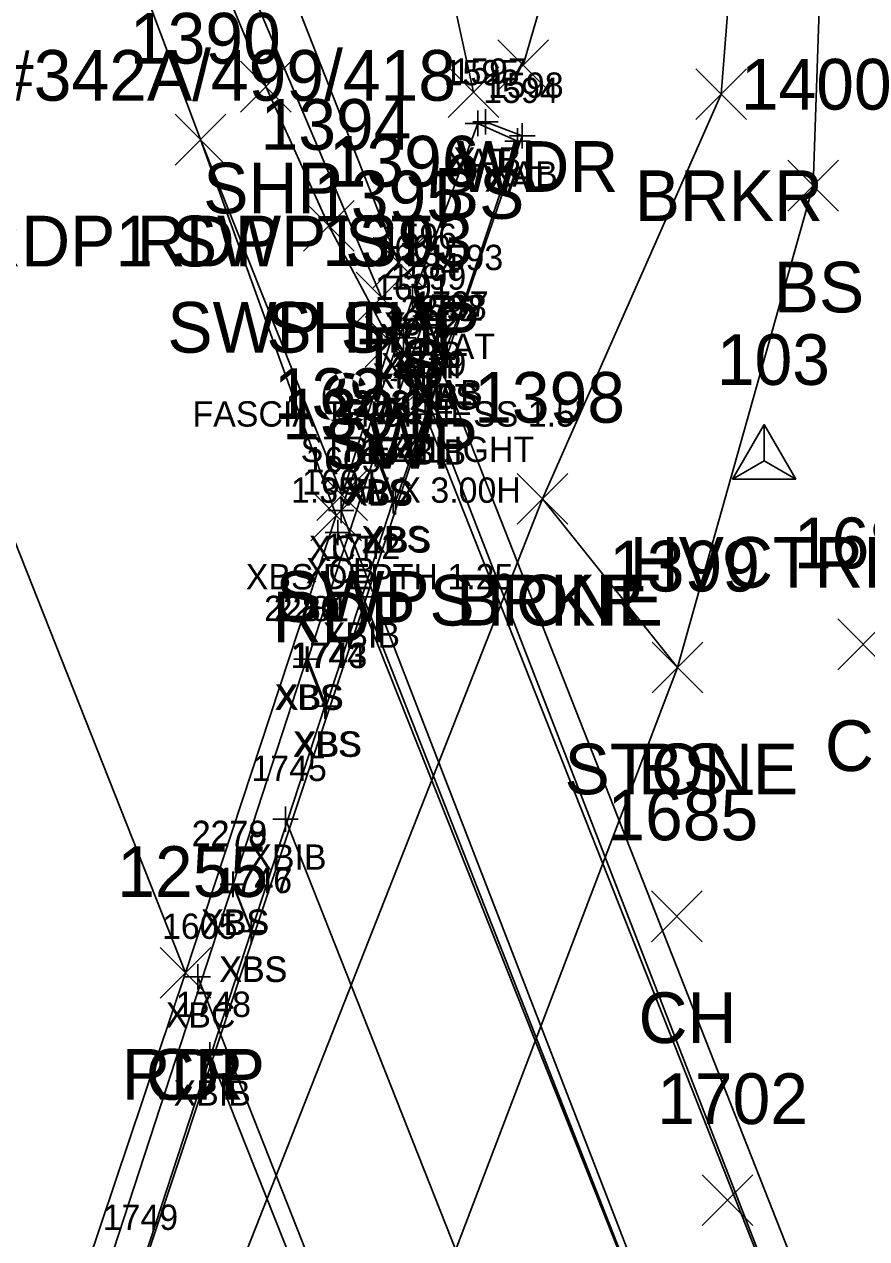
# Model space of a CAD drawing. Extents: x 1651305 to 1654558, y 539481 to 548441.
# Drawn here: x 1654313.41 to 1654346.64, y 544674.11 to 544722.01 of the extents above; entities that cross this region are included whole.
import ezdxf

# ---------------------------------------------------------------- set-up
doc = ezdxf.new("R2010")
doc.units = 0
for name, color, linetype in [('B_A', 7, 'Continuous'), ('B_C', 7, 'Continuous'), ('B_I', 7, 'Continuous'), ('B_TIC', 7, 'Continuous'), ('BB', 7, 'Continuous'), ('BDC', 7, 'Continuous'), ('BELB', 7, 'Continuous'), ('BF', 7, 'Continuous'), ('BR', 7, 'Continuous'), ('BSE', 7, 'Continuous'), ('BSUBM', 7, 'Continuous'), ('C_A', 7, 'Continuous'), ('C_I', 7, 'Continuous'), ('CPSM', 7, 'Continuous'), ('L_A', 7, 'Continuous'), ('L_I', 7, 'Continuous'), ('L_TIC', 7, 'Continuous'), ('LASF', 7, 'Continuous'), ('LAWA', 7, 'Continuous'), ('LAWE', 7, 'Continuous'), ('LELB', 7, 'Continuous'), ('P_A', 7, 'Continuous'), ('P_I', 7, 'Continuous'), ('P_TIC', 7, 'Continuous'), ('PET', 7, 'Continuous'), ('PRC', 7, 'Continuous'), ('PSP', 7, 'Continuous'), ('R_A', 7, 'Continuous'), ('R_I', 7, 'Continuous'), ('R_TIC', 7, 'Continuous'), ('RGR', 7, 'Continuous'), ('RSW', 7, 'Continuous'), ('U_C', 7, 'Continuous')]:
    doc.layers.add(name, color=color, linetype=linetype)

msp = doc.modelspace()

# ---------------------------------------------------------------- linework, layer by layer
at = {"layer": 'B_TIC'}
for p, q in [((1654331.298, 544718.108), (1654331.374, 544718.108)), ((1654331.607, 544718.167), (1654331.683, 544718.167)), ((1654332.861, 544717.411), (1654332.937, 544717.411)), ((1654333.056, 544717.613), (1654333.132, 544717.613)), ((1654328.88, 544711.655), (1654328.955, 544711.655)), ((1654328.88, 544711.655), (1654328.955, 544711.655)), ((1654328.721, 544711.198), (1654328.796, 544711.198)), ((1654330.672, 544710.818), (1654330.748, 544710.818)), ((1654329.233, 544710.496), (1654329.309, 544710.496)), ((1654329.218, 544710.048), (1654329.294, 544710.048)), ((1654329.218, 544710.048), (1654329.294, 544710.048)), ((1654329.218, 544710.048), (1654329.294, 544710.048)), ((1654328.368, 544709.646), (1654328.444, 544709.646)), ((1654329.887, 544708.806), (1654329.963, 544708.806)), ((1654329.894, 544708.829), (1654329.97, 544708.829)), ((1654329.894, 544708.829), (1654329.97, 544708.829)), ((1654330.023, 544708.857), (1654330.099, 544708.857)), ((1654330.098, 544708.982), (1654330.173, 544708.982)), ((1654328.993, 544708.249), (1654329.069, 544708.249)), ((1654329.22, 544706.64), (1654329.296, 544706.64)), ((1654327.25, 544705.075), (1654327.325, 544705.075)), ((1654327.332, 544705.024), (1654327.408, 544705.024)), ((1654327.966, 544703.224), (1654328.042, 544703.224)), ((1654328.048, 544703.173), (1654328.124, 544703.173)), ((1654325.907, 544702.843), (1654325.983, 544702.843)), ((1654325.779, 544701.967), (1654325.854, 544701.967)), ((1654326.614, 544699.426), (1654326.689, 544699.426)), ((1654324.544, 544696.977), (1654324.62, 544696.977)), ((1654324.597, 544696.97), (1654324.672, 544696.97)), ((1654325.261, 544695.126), (1654325.336, 544695.126)), ((1654325.313, 544695.119), (1654325.388, 544695.119)), ((1654323.714, 544690.667), (1654323.789, 544690.667)), ((1654321.641, 544688.089), (1654321.716, 544688.089)), ((1654321.656, 544688.103), (1654321.731, 544688.103)), ((1654322.357, 544686.238), (1654322.433, 544686.238)), ((1654322.372, 544686.252), (1654322.448, 544686.252)), ((1654320.252, 544684.44), (1654320.327, 544684.44)), ((1654320.725, 544681.361), (1654320.801, 544681.361))]:
    msp.add_line(p, q, dxfattribs=at)
for points in [[(1654331.295, 544717.608), (1654331.295, 544718.608)], [(1654331.604, 544717.667), (1654331.604, 544718.667)], [(1654330.795, 544718.108), (1654331.795, 544718.108)], [(1654331.104, 544718.167), (1654332.104, 544718.167)], [(1654332.858, 544716.911), (1654332.858, 544717.911)], [(1654333.053, 544717.113), (1654333.053, 544718.113)], [(1654332.358, 544717.411), (1654333.358, 544717.411)], [(1654332.553, 544717.613), (1654333.553, 544717.613)], [(1654328.876, 544711.155), (1654328.876, 544712.155)], [(1654328.876, 544711.155), (1654328.876, 544712.155)], [(1654328.376, 544711.655), (1654329.376, 544711.655)], [(1654328.376, 544711.655), (1654329.376, 544711.655)], [(1654328.717, 544710.698), (1654328.717, 544711.698)], [(1654328.217, 544711.198), (1654329.217, 544711.198)], [(1654330.669, 544710.318), (1654330.669, 544711.318)], [(1654329.23, 544709.996), (1654329.23, 544710.996)], [(1654330.169, 544710.818), (1654331.169, 544710.818)], [(1654328.73, 544710.496), (1654329.73, 544710.496)], [(1654329.215, 544709.548), (1654329.215, 544710.548)], [(1654329.215, 544709.548), (1654329.215, 544710.548)], [(1654329.215, 544709.548), (1654329.215, 544710.548)], [(1654328.365, 544709.146), (1654328.365, 544710.146)], [(1654328.715, 544710.048), (1654329.715, 544710.048)], [(1654328.715, 544710.048), (1654329.715, 544710.048)], [(1654328.715, 544710.048), (1654329.715, 544710.048)], [(1654327.865, 544709.646), (1654328.865, 544709.646)], [(1654329.884, 544708.306), (1654329.884, 544709.306)], [(1654329.891, 544708.329), (1654329.891, 544709.329)], [(1654329.891, 544708.329), (1654329.891, 544709.329)], [(1654330.02, 544708.357), (1654330.02, 544709.357)], [(1654330.094, 544708.482), (1654330.094, 544709.482)], [(1654328.99, 544707.749), (1654328.99, 544708.749)], [(1654329.384, 544708.806), (1654330.384, 544708.806)], [(1654329.391, 544708.829), (1654330.391, 544708.829)], [(1654329.391, 544708.829), (1654330.391, 544708.829)], [(1654329.52, 544708.857), (1654330.52, 544708.857)], [(1654329.594, 544708.982), (1654330.594, 544708.982)], [(1654328.49, 544708.249), (1654329.49, 544708.249)], [(1654329.217, 544706.14), (1654329.217, 544707.14)], [(1654328.717, 544706.64), (1654329.717, 544706.64)], [(1654327.246, 544704.575), (1654327.246, 544705.575)], [(1654327.329, 544704.524), (1654327.329, 544705.524)], [(1654326.746, 544705.075), (1654327.746, 544705.075)], [(1654326.829, 544705.024), (1654327.829, 544705.024)], [(1654327.963, 544702.724), (1654327.963, 544703.724)], [(1654328.045, 544702.673), (1654328.045, 544703.673)], [(1654325.904, 544702.343), (1654325.904, 544703.343)], [(1654327.463, 544703.224), (1654328.463, 544703.224)], [(1654327.545, 544703.173), (1654328.545, 544703.173)], [(1654325.404, 544702.843), (1654326.404, 544702.843)], [(1654325.775, 544701.467), (1654325.775, 544702.467)], [(1654325.275, 544701.967), (1654326.275, 544701.967)], [(1654326.61, 544698.926), (1654326.61, 544699.926)], [(1654326.11, 544699.426), (1654327.11, 544699.426)], [(1654324.541, 544696.477), (1654324.541, 544697.477)], [(1654324.593, 544696.47), (1654324.593, 544697.47)], [(1654324.041, 544696.977), (1654325.041, 544696.977)], [(1654324.093, 544696.97), (1654325.093, 544696.97)], [(1654325.257, 544694.626), (1654325.257, 544695.626)], [(1654325.309, 544694.619), (1654325.309, 544695.619)], [(1654324.757, 544695.126), (1654325.757, 544695.126)], [(1654324.809, 544695.119), (1654325.809, 544695.119)], [(1654323.71, 544690.167), (1654323.71, 544691.167)], [(1654323.21, 544690.667), (1654324.21, 544690.667)], [(1654321.637, 544687.589), (1654321.637, 544688.589)], [(1654321.652, 544687.603), (1654321.652, 544688.603)], [(1654321.137, 544688.089), (1654322.137, 544688.089)], [(1654321.152, 544688.103), (1654322.152, 544688.103)], [(1654322.354, 544685.738), (1654322.354, 544686.738)], [(1654322.369, 544685.752), (1654322.369, 544686.752)], [(1654321.854, 544686.238), (1654322.854, 544686.238)], [(1654321.869, 544686.252), (1654322.869, 544686.252)], [(1654320.248, 544683.94), (1654320.248, 544684.94)], [(1654319.748, 544684.44), (1654320.748, 544684.44)], [(1654320.722, 544680.861), (1654320.722, 544681.861)], [(1654320.222, 544681.361), (1654321.222, 544681.361)]]:
    msp.add_lwpolyline(points, dxfattribs=at)
at = {"layer": 'BB'}
for points in [[(1654329.217, 544706.64), (1654357.619, 544634.79)], [(1654326.61, 544699.426), (1654355.293, 544627.225)], [(1654323.71, 544690.667), (1654352.287, 544618.374)], [(1654320.722, 544681.361), (1654349.259, 544609.535)]]:
    msp.add_lwpolyline(points, dxfattribs=at)
at = {"layer": 'BDC'}
for points in [[(1654329.215, 544710.048), (1654328.717, 544711.198), (1654325.904, 544702.843), (1654343.99, 544656.168), (1654356.815, 544626.314), (1654359.561, 544633.364), (1654359.473, 544633.501)], [(1654325.775, 544701.967), (1654343.848, 544655.963), (1654356.322, 544625.929)]]:
    msp.add_lwpolyline(points, dxfattribs=at)
at = {"layer": 'BELB'}
msp.add_lwpolyline([(1654320.248, 544684.44), (1654335.991, 544644.535), (1654350.441, 544607.388)], dxfattribs=at)
at = {"layer": 'BF'}
msp.add_lwpolyline([(1654329.215, 544710.048), (1654348.537, 544660.985), (1654359.473, 544633.501)], dxfattribs=at)
at = {"layer": 'BR'}
msp.add_lwpolyline([(1654329.215, 544710.048), (1654328.365, 544709.646), (1654348.062, 544658.92), (1654358.364, 544633.155), (1654359.473, 544633.501)], dxfattribs=at)
at = {"layer": 'BSE'}
for points in [[(1654330.02, 544708.857), (1654328.045, 544703.173), (1654327.963, 544703.224), (1654325.309, 544695.119), (1654325.257, 544695.126), (1654322.369, 544686.252), (1654322.354, 544686.238), (1654314.152, 544661.138), (1654313.436, 544662.989), (1654321.637, 544688.089), (1654321.652, 544688.103), (1654324.541, 544696.977), (1654324.593, 544696.97), (1654327.246, 544705.075), (1654327.329, 544705.024), (1654329.23, 544710.496), (1654329.884, 544708.806)], [(1654329.884, 544708.806), (1654330.02, 544708.857)], [(1654327.246, 544705.075), (1654327.963, 544703.224)], [(1654327.329, 544705.024), (1654328.045, 544703.173)], [(1654324.541, 544696.977), (1654325.257, 544695.126)], [(1654324.593, 544696.97), (1654325.309, 544695.119)], [(1654321.637, 544688.089), (1654322.354, 544686.238)], [(1654321.652, 544688.103), (1654322.369, 544686.252)]]:
    msp.add_lwpolyline(points, dxfattribs=at)
at = {"layer": 'BSUBM'}
for points in [[(1654331.604, 544718.167), (1654333.053, 544717.613), (1654330.094, 544708.982), (1654313.851, 544660.207)], [(1654329.891, 544708.829), (1654330.669, 544710.818), (1654332.858, 544717.411), (1654331.295, 544718.108), (1654328.876, 544711.655)], [(1654329.891, 544708.829), (1654328.876, 544711.655)]]:
    msp.add_lwpolyline(points, dxfattribs=at)
at = {"layer": 'CPSM'}
for p, q in [((1654341.348, 544704.069), (1654342.598, 544706.234)), ((1654343.848, 544704.069), (1654342.598, 544706.234)), ((1654342.598, 544704.79), (1654342.598, 544706.234)), ((1654341.348, 544704.069), (1654342.598, 544704.79)), ((1654342.598, 544704.79), (1654342.598, 544704.79)), ((1654342.598, 544704.79), (1654343.848, 544704.069)), ((1654341.348, 544704.069), (1654343.848, 544704.069))]:
    msp.add_line(p, q, dxfattribs=at)
at = {"layer": 'L_TIC'}
for points in [[(1654332.089, 544719.406), (1654334.089, 544721.406)], [(1654334.089, 544719.406), (1654332.089, 544721.406)], [(1654330.123, 544718.343), (1654332.123, 544720.343)], [(1654332.123, 544718.343), (1654330.123, 544720.343)], [(1654339.893, 544718.253), (1654341.893, 544720.253)], [(1654341.893, 544718.253), (1654339.893, 544720.253)], [(1654343.529, 544714.65), (1654345.529, 544716.65)], [(1654345.529, 544714.65), (1654343.529, 544716.65)], [(1654327.163, 544711.614), (1654329.163, 544713.614)], [(1654329.163, 544711.614), (1654327.163, 544713.614)], [(1654332.845, 544702.3), (1654334.845, 544704.3)], [(1654334.845, 544702.3), (1654332.845, 544704.3)], [(1654332.845, 544702.3), (1654334.845, 544704.3)], [(1654334.845, 544702.3), (1654332.845, 544704.3)], [(1654345.503, 544696.559), (1654347.503, 544698.559)], [(1654347.503, 544696.559), (1654345.503, 544698.559)], [(1654338.174, 544695.643), (1654340.174, 544697.643)], [(1654340.174, 544695.643), (1654338.174, 544697.643)], [(1654338.174, 544695.643), (1654340.174, 544697.643)], [(1654340.174, 544695.643), (1654338.174, 544697.643)], [(1654338.147, 544685.83), (1654340.147, 544687.83)], [(1654340.147, 544685.83), (1654338.147, 544687.83)], [(1654340.142, 544674.636), (1654342.142, 544676.636)], [(1654342.142, 544674.636), (1654340.142, 544676.636)]]:
    msp.add_lwpolyline(points, dxfattribs=at)
at = {"layer": 'LASF'}
msp.add_lwpolyline([(1654333.845, 544703.3), (1654339.174, 544696.643)], dxfattribs=at)
at = {"layer": 'LAWA'}
msp.add_lwpolyline([(1654333.089, 544720.406), (1654339.568, 544742.787), (1654339.926, 544774.824), (1654333.777, 544809.516), (1654332.911, 544836.907), (1654333.19, 544866.217)], dxfattribs=at)
at = {"layer": 'LAWE'}
msp.add_lwpolyline([(1654242.515, 544465.967), (1654256.87, 544483.548), (1654283.123, 544539.875), (1654291.834, 544564.241), (1654301.763, 544593.784), (1654310.979, 544627.694), (1654314.699, 544654.654), (1654333.845, 544703.3), (1654340.893, 544719.253), (1654343.001, 544745.948), (1654343.543, 544777.003), (1654341.256, 544814.623), (1654342.705, 544842.641), (1654342.649, 544866.803)], dxfattribs=at)
at = {"layer": 'LELB'}
for points in [[(1654268.864, 544879.178), (1654276.493, 544842.278), (1654286.118, 544815.622), (1654299.147, 544783.593), (1654310.71, 544759.789), (1654316.885, 544741.298), (1654328.163, 544712.614)], [(1654321.982, 544868.568), (1654300.331, 544866.144), (1654280.17, 544869.383), (1654284.965, 544845.051), (1654295.376, 544825.082), (1654318.777, 544790.661), (1654321.652, 544762.863), (1654331.123, 544719.343)], [(1654243.655, 544463.614), (1654257.64, 544478.05), (1654284.349, 544538.419), (1654294.462, 544561.387), (1654312.806, 544626.029), (1654318.85, 544643.272), (1654339.174, 544696.643), (1654344.529, 544715.65), (1654345.587, 544746.872), (1654345.745, 544776.719), (1654344.633, 544815.202), (1654344.44, 544841.842), (1654343.526, 544866.969)]]:
    msp.add_lwpolyline(points, dxfattribs=at)
at = {"layer": 'P_TIC'}
for points in [[(1654321.93, 544718.555), (1654323.93, 544720.555)], [(1654323.93, 544718.555), (1654321.93, 544720.555)], [(1654319.353, 544716.464), (1654321.353, 544718.464)], [(1654321.353, 544716.464), (1654319.353, 544718.464)], [(1654324.421, 544713.063), (1654326.421, 544715.063)], [(1654326.421, 544713.063), (1654324.421, 544715.063)], [(1654324.712, 544701.64), (1654326.712, 544703.64)], [(1654326.712, 544701.64), (1654324.712, 544703.64)], [(1654324.712, 544701.64), (1654326.712, 544703.64)], [(1654326.712, 544701.64), (1654324.712, 544703.64)], [(1654318.767, 544683.597), (1654320.767, 544685.597)], [(1654320.767, 544683.597), (1654318.767, 544685.597)], [(1654318.767, 544683.597), (1654320.767, 544685.597)], [(1654320.767, 544683.597), (1654318.767, 544685.597)]]:
    msp.add_lwpolyline(points, dxfattribs=at)
at = {"layer": 'PET'}
for points in [[(1654139.13, 545176.501), (1654150.393, 545147.194), (1654157.161, 545131.709), (1654170.764, 545099.134), (1654178.155, 545080.649), (1654186.439, 545060.962), (1654201.827, 545022.365), (1654207.176, 545004.715), (1654219.138, 544973.235), (1654242.36, 544920.072), (1654247.532, 544907.575), (1654259.279, 544878.108), (1654268.455, 544853.759), (1654271.522, 544840.232), (1654282.762, 544813.426), (1654295.449, 544782.265), (1654306.751, 544753.721), (1654320.353, 544717.464), (1654325.712, 544702.64)], [(1654112.873, 545166.538), (1654122.035, 545140.208), (1654132.622, 545111.941), (1654135.362, 545108.194), (1654138.441, 545103.483), (1654151.391, 545069.682), (1654150.584, 545065.43), (1654160.56, 545041.116), (1654174.104, 545006.911), (1654181.292, 544989.927), (1654184.888, 544987.01), (1654195.032, 544961.541), (1654207.758, 544928.164), (1654222.993, 544890.413), (1654239.031, 544850.694), (1654252.069, 544818.679), (1654270.718, 544773.03), (1654287.358, 544732.427), (1654297.759, 544708.463), (1654313.88, 544667.099), (1654319.767, 544684.597), (1654325.712, 544702.64)]]:
    msp.add_lwpolyline(points, dxfattribs=at)
at = {"layer": 'PRC'}
msp.add_lwpolyline([(1654126.316, 545171.737), (1654141.33, 545133.412), (1654151.931, 545107.487), (1654165.206, 545072.693), (1654175.565, 545046.61), (1654188.965, 545011.94), (1654198.023, 544989.456), (1654207.449, 544965.611), (1654220.746, 544933.068), (1654235.659, 544895.022), (1654251.308, 544856.189), (1654265.059, 544822.156), (1654283.023, 544778.205), (1654298.758, 544737.492), (1654308.597, 544712.81), (1654319.767, 544684.597)], dxfattribs=at)
at = {"layer": 'PSP'}
msp.add_lwpolyline([(1654296.828, 544784.807), (1654308.935, 544754.714), (1654316.682, 544734.635), (1654322.93, 544719.555), (1654325.421, 544714.063)], dxfattribs=at)
at = {"layer": 'R_TIC'}
for points in [[(1654319.353, 544716.464), (1654321.353, 544718.464)], [(1654321.353, 544716.464), (1654319.353, 544718.464)], [(1654324.421, 544713.063), (1654326.421, 544715.063)], [(1654326.421, 544713.063), (1654324.421, 544715.063)], [(1654326.493, 544710.239), (1654328.493, 544712.239)], [(1654328.493, 544710.239), (1654326.493, 544712.239)], [(1654326.848, 544708.484), (1654328.848, 544710.484)], [(1654328.848, 544708.484), (1654326.848, 544710.484)], [(1654324.944, 544702.446), (1654326.944, 544704.446)], [(1654326.944, 544702.446), (1654324.944, 544704.446)]]:
    msp.add_lwpolyline(points, dxfattribs=at)
at = {"layer": 'RGR'}
msp.add_lwpolyline([(1654318.623, 544746.668), (1654316.885, 544741.298), (1654318.26, 544733.069), (1654327.493, 544711.239)], dxfattribs=at)
at = {"layer": 'RSW'}
msp.add_lwpolyline([(1654320.353, 544717.464), (1654325.944, 544703.446), (1654327.848, 544709.484), (1654325.421, 544714.063)], dxfattribs=at)

# ---------------------------------------------------------------- texts
at = {"layer": 'B_A'}
for s, p in [('XAT', (1654330, 544716.108)), ('XAB', (1654330.324, 544716.167)), ('XAT', (1654331.562, 544715.411)), ('XAB', (1654331.773, 544715.613)), ('XAT', (1654327.581, 544709.655)), ('XAT', (1654327.581, 544709.655)), ('XCT', (1654327.438, 544709.198)), ('XAT', (1654329.374, 544708.818)), ('XBS', (1654327.97, 544708.496)), ('XFAT', (1654327.471, 544708.048)), ('XCT', (1654327.935, 544708.048)), ('XRF', (1654327.975, 544708.048)), ('XRF', (1654327.124, 544707.646)), ('XAT', (1654328.596, 544706.829)), ('XAT', (1654328.596, 544706.829)), ('XBS', (1654328.624, 544706.806)), ('XBS', (1654328.76, 544706.857)), ('XAB', (1654328.815, 544706.982)), ('XSF', (1654327.75, 544706.249)), ('XBIB', (1654327.788, 544704.64)), ('XBS', (1654325.987, 544703.075)), ('XBS', (1654326.069, 544703.024)), ('XBS', (1654326.703, 544701.224)), ('XBS', (1654326.785, 544701.173)), ('XCT', (1654324.624, 544700.843)), ('XCB', (1654324.512, 544699.967)), ('XBIB', (1654325.181, 544697.426)), ('XBS', (1654323.281, 544694.977)), ('XBS', (1654323.333, 544694.97)), ('XBS', (1654323.997, 544693.126)), ('XBS', (1654324.05, 544693.119)), ('XBIB', (1654322.281, 544688.667)), ('XBS', (1654320.377, 544686.089)), ('XBS', (1654320.393, 544686.103)), ('XBS', (1654321.109, 544684.252)), ('XBS', (1654321.094, 544684.238)), ('XBC', (1654318.985, 544682.44)), ('XBIB', (1654319.293, 544679.361))]:
    msp.add_text(s, height=1, dxfattribs=at).set_placement(p)
at = {"layer": 'B_C'}
for s, p in [("FASCIA THICKNESS 1.5'", (1654320.042, 544706.146)), ('STREETLIGHT', (1654324.309, 544704.749)), ('1.35W X 3.00H', (1654323.926, 544703.14)), ('XBS DEPTH 1.25', (1654322.144, 544699.724))]:
    msp.add_text(s, height=1, dxfattribs=at).set_placement(p)
at = {"layer": 'B_I'}
for s, p in [('1595', (1654329.949, 544719.608)), ('1597', (1654330.257, 544719.667)), ('1594', (1654331.511, 544718.911)), ('1598', (1654331.706, 544719.113)), ('1596', (1654327.502, 544713.155)), ('1596', (1654327.502, 544713.155)), ('1600', (1654327.265, 544712.698)), ('1593', (1654329.323, 544712.318)), ('2284', (1654327.6, 544711.996)), ('1599', (1654327.865, 544711.548)), ('1599', (1654327.865, 544711.548)), ('1599', (1654327.865, 544711.548)), ('1601', (1654327.239, 544711.146)), ('2285', (1654328.254, 544710.306)), ('1592', (1654328.545, 544710.329)), ('1592', (1654328.545, 544710.329)), ('1738', (1654328.673, 544710.357)), ('1737', (1654328.748, 544710.482)), ('1602', (1654327.58, 544709.749)), ('1739', (1654327.867, 544708.14)), ('2282', (1654325.617, 544706.575)), ('2283', (1654325.699, 544706.524)), ('1740', (1654326.655, 544704.673)), ('1741', (1654326.9, 544704.724)), ('1603', (1654324.495, 544704.343)), ('1604', (1654324.366, 544703.467)), ('1742', (1654325.264, 544700.926)), ('2280', (1654322.868, 544698.477)), ('2281', (1654323.247, 544698.47)), ('1744', (1654323.911, 544696.626)), ('1743', (1654323.963, 544696.619)), ('1745', (1654322.364, 544692.167)), ('2278', (1654320.007, 544689.589)), ('2279', (1654320.019, 544689.603)), ('1746', (1654320.995, 544687.752)), ('1747', (1654321.007, 544687.738)), ('1605', (1654318.839, 544685.94)), ('1748', (1654319.375, 544682.861)), ('1749', (1654316.501, 544674.461))]:
    msp.add_text(s, height=1, dxfattribs=at).set_placement(p)
at = {"layer": 'C_A'}
msp.add_text('HVCTRL', height=2, dxfattribs=at).set_placement((1654337.291, 544699.79))
at = {"layer": 'C_I'}
msp.add_text('103', height=2, dxfattribs=at).set_placement((1654340.725, 544707.79))
at = {"layer": 'L_A'}
for s, p in [('WDR', (1654330.451, 544715.406)), ('BS', (1654329.564, 544714.343)), ('BRKR', (1654337.484, 544714.253)), ('BS', (1654342.97, 544710.65)), ('TS', (1654326.573, 544707.614)), ('STONE', (1654329.389, 544698.3)), ('BRKR', (1654330.436, 544698.3)), ('CH', (1654344.991, 544692.559)), ('STONE', (1654334.718, 544691.643)), ('BS', (1654337.615, 544691.643)), ('CH', (1654337.635, 544681.83))]:
    msp.add_text(s, height=2, dxfattribs=at).set_placement(p)
at = {"layer": 'L_I'}
for s, p in [('1400', (1654341.671, 544718.65)), ('1396', (1654325.416, 544715.614)), ('1398', (1654331.152, 544706.3)), ('1398', (1654331.152, 544706.3)), ('1684', (1654343.763, 544700.559)), ('1399', (1654336.474, 544699.643)), ('1399', (1654336.474, 544699.643)), ('1685', (1654336.407, 544689.83)), ('1702', (1654338.371, 544678.636))]:
    msp.add_text(s, height=2, dxfattribs=at).set_placement(p)
at = {"layer": 'P_A'}
for s, p in [('SHP', (1654320.465, 544714.555)), ('RDP', (1654317.841, 544712.464)), ('SHP', (1654322.956, 544709.063)), ('RDP', (1654323.2, 544697.64)), ('RDP', (1654323.2, 544697.64)), ('RDP', (1654317.255, 544679.597)), ('CR', (1654318.2, 544679.597))]:
    msp.add_text(s, height=2, dxfattribs=at).set_placement(p)
at = {"layer": 'P_I'}
for s, p in [('1390', (1654317.574, 544720.464)), ('1394', (1654322.728, 544717.063)), ('1391', (1654323.586, 544705.64)), ('1391', (1654323.586, 544705.64)), ('1255', (1654317.074, 544687.597)), ('1255', (1654317.074, 544687.597))]:
    msp.add_text(s, height=2, dxfattribs=at).set_placement(p)
at = {"layer": 'R_A'}
for s, p in [('RDP1 SWP ST', (1654311.353, 544712.464)), ('SWP SHP', (1654319.051, 544709.063)), ('GRL', (1654325.036, 544706.239)), ('SWP', (1654325.21, 544704.484)), ('SWP', (1654323.306, 544698.446))]:
    msp.add_text(s, height=2, dxfattribs=at).set_placement(p)
at = {"layer": 'R_I'}
for s, p in [('1390', (1654317.574, 544720.464)), ('1394', (1654322.728, 544717.063)), ('1395', (1654324.8, 544714.239)), ('1393', (1654325.155, 544712.484)), ('1392', (1654323.251, 544706.446))]:
    msp.add_text(s, height=2, dxfattribs=at).set_placement(p)
at = {"layer": 'U_C'}
msp.add_text('#342A/499/418', height=2, dxfattribs=at).set_placement((1654312.293, 544718.999))

doc.saveas('drawing.dxf')
